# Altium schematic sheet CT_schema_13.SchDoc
size 147 x 119 mm
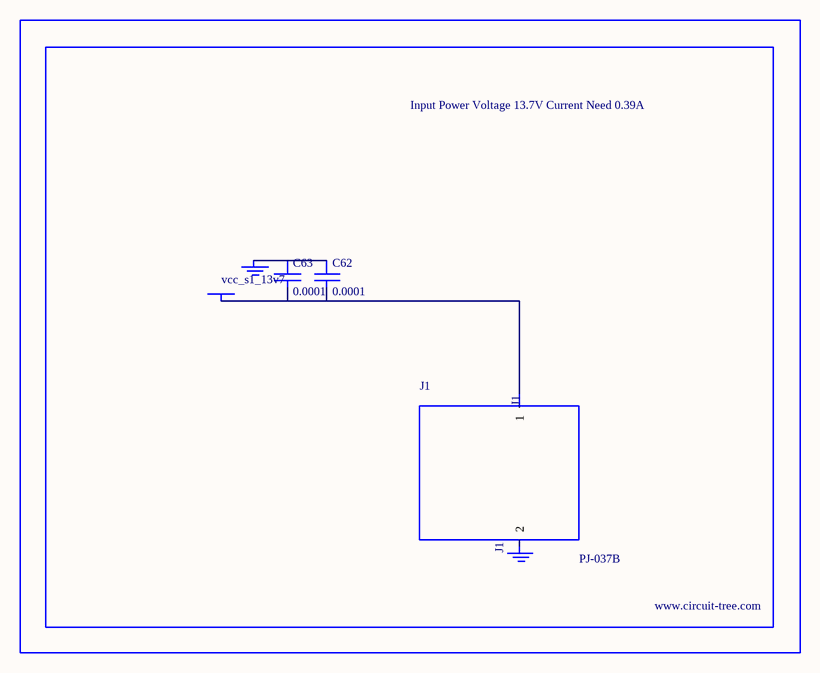
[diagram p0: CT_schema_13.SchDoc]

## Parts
BORDER12  (no value)
C62  0.0001  [EXV-9H]
C63  0.0001  [EXV-9H]
GND_INSTANCE_12_0  (no value)
GND_INSTANCE_12_1  (no value)
J1  PJ-037B  [PJ-037B_PACKAGE]
POWER_INSTANCE_12_0  vcc_s1_13v7

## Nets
NetC62_1: C62.1 C63.1 GND_INSTANCE_12_0.0(GND)
NetC62_2: C62.2 C63.2 J1.1 POWER_INSTANCE_12_0.0(PWR)

Not connected (* = marked no-connect by the designer): GND_INSTANCE_12_1 0(GND); J1 2

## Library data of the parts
BORDER12 = BORDER_PAGE12
C62 C63 = EDK107M035A9HAA
GND_INSTANCE_12_0 GND_INSTANCE_12_1 = GND
POWER_INSTANCE_12_0 = PWR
